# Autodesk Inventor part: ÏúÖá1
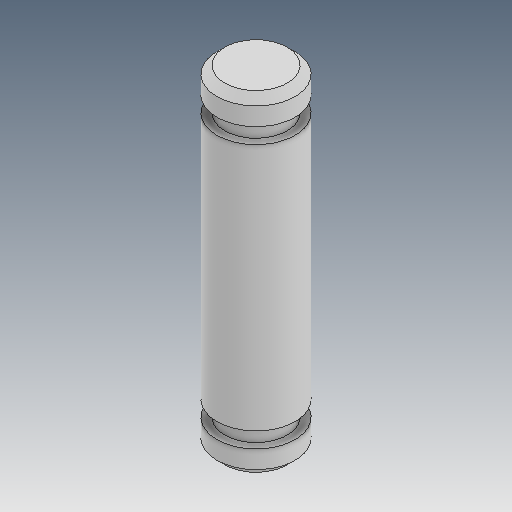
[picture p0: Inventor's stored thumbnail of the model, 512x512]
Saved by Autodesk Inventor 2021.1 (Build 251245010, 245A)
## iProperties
Created: 2015-08
Part Number: ÏúÖá1
Material: Ogólny
Document SubType Name: Modeling
Designer: user
Density: 1 g/cm^3
Appearance: Domyślna
Author: user
Revision Number: ÈÎºÎ
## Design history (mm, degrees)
feature "Ðý×ª1"
node "Bryła1"
